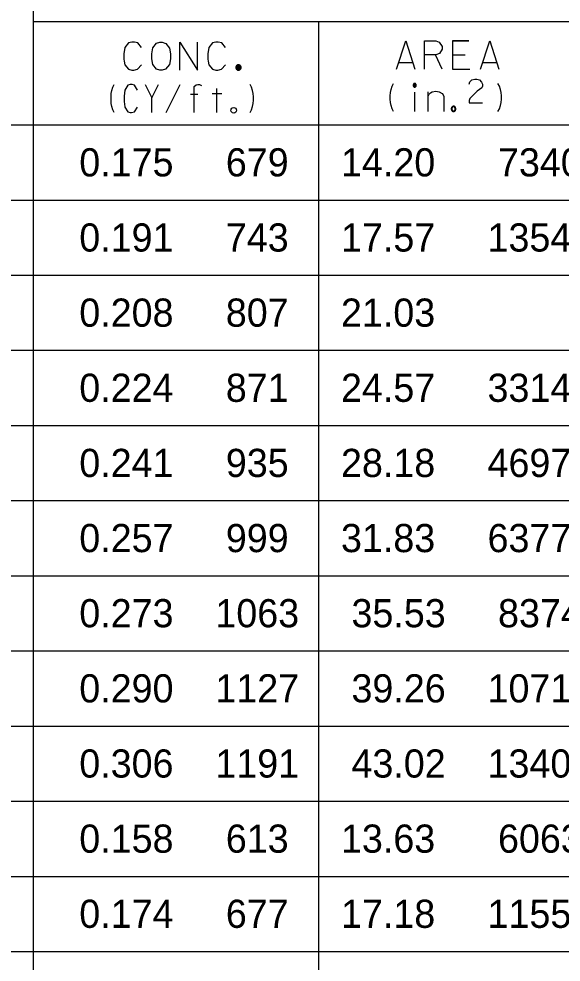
# Model space of a CAD drawing. Extents: x 635698 to 639877, y 296617 to 300175.
# Drawn here: x 639197.6 to 639255.4, y 298708.2 to 298808.6 of the extents above; entities that cross this region are included whole.
import ezdxf

# ---------------------------------------------------------------- set-up
doc = ezdxf.new("R2010")
doc.units = 0
for name, color, linetype in [('1', 7, 'Continuous'), ('2', 7, 'Continuous'), ('3', 7, 'Continuous')]:
    doc.layers.add(name, color=color, linetype=linetype)

msp = doc.modelspace()

# ---------------------------------------------------------------- linework, layer by layer
at = {"layer": '1'}
msp.add_circle((639220.51, 298798.88), 0.301, dxfattribs=at)
at = {"layer": '2'}
for p, q in [((639199.16, 298814.79), (639199.16, 298581.29)), ((639405.11, 298808.29), (639199.16, 298808.29)), ((639229.55, 298808.29), (639229.55, 298581.29)), ((639405.11, 298797.29), (638853.27, 298797.29)), ((639405.11, 298789.29), (638853.27, 298789.29)), ((639405.11, 298781.29), (638853.27, 298781.29)), ((639405.11, 298773.29), (638853.27, 298773.29)), ((639405.11, 298765.29), (638853.27, 298765.29)), ((639405.11, 298757.29), (638853.27, 298757.29)), ((639405.11, 298749.29), (638853.27, 298749.29)), ((639405.11, 298741.29), (638853.27, 298741.29)), ((639405.11, 298733.29), (638853.27, 298733.29)), ((639405.11, 298725.29), (638853.27, 298725.29)), ((639405.11, 298725.29), (638853.27, 298725.29)), ((639405.11, 298717.29), (638853.27, 298717.29)), ((639405.11, 298709.29), (638853.27, 298709.29))]:
    msp.add_line(p, q, dxfattribs=at)
at = {"layer": '3'}
for points in [[(639210.68, 298805.56), (639210.31, 298806.06), (639209.93, 298806.15), (639209.67, 298806.15), (639209.31, 298806.06), (639208.91, 298805.56), (639208.82, 298804.9), (639208.82, 298804.55), (639208.82, 298804.31), (639208.84, 298804.1), (639208.91, 298803.72), (639209.31, 298803.25), (639209.67, 298803.15), (639209.88, 298803.15), (639210.28, 298803.25), (639210.68, 298803.72)], [(639212.65, 298806.15), (639212.88, 298806.15), (639213.29, 298805.99), (639213.66, 298805.49), (639213.76, 298804.9), (639213.76, 298804.36), (639213.66, 298803.77), (639213.26, 298803.27), (639212.88, 298803.15), (639212.65, 298803.15), (639212.29, 298803.27), (639211.89, 298803.77), (639211.8, 298804.36), (639211.8, 298804.9), (639211.89, 298805.52), (639212.29, 298806.01), (639212.65, 298806.15)], [(639214.78, 298803.15), (639214.78, 298806.15), (639216.64, 298803.15), (639216.64, 298806.15)], [(639219.62, 298805.56), (639219.24, 298806.06), (639218.87, 298806.15), (639218.61, 298806.15), (639218.25, 298806.06), (639217.85, 298805.56), (639217.75, 298804.9), (639217.75, 298804.55), (639217.75, 298804.31), (639217.78, 298804.1), (639217.85, 298803.72), (639218.25, 298803.25), (639218.61, 298803.15), (639218.82, 298803.15), (639219.22, 298803.25), (639219.62, 298803.72)], [(639237.86, 298803.27), (639238.85, 298806.27), (639239.82, 298803.27)], [(639240.84, 298803.27), (639240.84, 298806.27), (639242.04, 298806.27), (639242.4, 298806.15), (639242.7, 298805.68), (639242.7, 298805.39), (639242.42, 298804.92), (639242.04, 298804.8), (639240.84, 298804.8)], [(639245.54, 298806.27), (639243.82, 298806.27), (639243.82, 298803.27), (639245.66, 298803.27)], [(639243.82, 298806.27), (639245.54, 298806.27)], [(639246.79, 298803.27), (639247.79, 298806.27), (639248.76, 298803.27)], [(639242.7, 298803.27), (639242.02, 298804.8)], [(639243.82, 298804.78), (639245.17, 298804.78)], [(639243.82, 298804.78), (639245.17, 298804.78)], [(639238.09, 298803.98), (639239.58, 298803.98)], [(639247.03, 298803.98), (639248.52, 298803.98)], [(639221.3, 298803.44), (639221.3, 298803.47), (639221.3, 298803.5), (639221.29, 298803.53), (639221.28, 298803.55), (639221.27, 298803.58), (639221.25, 298803.61), (639221.23, 298803.63), (639221.21, 298803.65), (639221.19, 298803.67), (639221.16, 298803.69), (639221.14, 298803.7), (639221.11, 298803.71), (639221.08, 298803.72), (639221.05, 298803.72), (639221.02, 298803.72), (639220.99, 298803.72), (639220.96, 298803.72), (639220.93, 298803.71), (639220.9, 298803.7), (639220.88, 298803.69), (639220.85, 298803.67), (639220.83, 298803.65), (639220.81, 298803.63), (639220.79, 298803.61), (639220.77, 298803.58), (639220.76, 298803.55), (639220.75, 298803.53), (639220.74, 298803.5), (639220.74, 298803.47), (639220.73, 298803.44), (639220.74, 298803.41), (639220.74, 298803.38), (639220.75, 298803.35), (639220.76, 298803.32), (639220.77, 298803.3), (639220.79, 298803.27), (639220.81, 298803.25), (639220.83, 298803.23), (639220.85, 298803.21), (639220.88, 298803.19), (639220.9, 298803.18), (639220.93, 298803.17), (639220.96, 298803.16), (639220.99, 298803.15), (639221.02, 298803.15), (639221.05, 298803.15), (639221.08, 298803.16), (639221.11, 298803.17), (639221.14, 298803.18), (639221.16, 298803.19), (639221.19, 298803.21), (639221.21, 298803.23), (639221.23, 298803.25), (639221.25, 298803.27), (639221.27, 298803.3), (639221.28, 298803.32), (639221.29, 298803.35), (639221.3, 298803.38), (639221.3, 298803.41), (639221.3, 298803.44)], [(639221.24, 298803.44), (639221.24, 298803.46), (639221.24, 298803.48), (639221.23, 298803.51), (639221.23, 298803.53), (639221.21, 298803.55), (639221.2, 298803.57), (639221.19, 298803.59), (639221.17, 298803.61), (639221.15, 298803.62), (639221.13, 298803.63), (639221.11, 298803.64), (639221.09, 298803.65), (639221.07, 298803.66), (639221.04, 298803.66), (639221.02, 298803.66), (639221, 298803.66), (639220.97, 298803.66), (639220.95, 298803.65), (639220.93, 298803.64), (639220.91, 298803.63), (639220.89, 298803.62), (639220.87, 298803.61), (639220.85, 298803.59), (639220.84, 298803.57), (639220.82, 298803.55), (639220.81, 298803.53), (639220.8, 298803.51), (639220.8, 298803.48), (639220.8, 298803.46), (639220.79, 298803.44), (639220.8, 298803.41), (639220.8, 298803.39), (639220.8, 298803.37), (639220.81, 298803.35), (639220.82, 298803.33), (639220.84, 298803.31), (639220.85, 298803.29), (639220.87, 298803.27), (639220.89, 298803.26), (639220.91, 298803.24), (639220.93, 298803.23), (639220.95, 298803.22), (639220.97, 298803.22), (639221, 298803.21), (639221.02, 298803.21), (639221.04, 298803.21), (639221.07, 298803.22), (639221.09, 298803.22), (639221.11, 298803.23), (639221.13, 298803.24), (639221.15, 298803.26), (639221.17, 298803.27), (639221.19, 298803.29), (639221.2, 298803.31), (639221.21, 298803.33), (639221.23, 298803.35), (639221.23, 298803.37), (639221.24, 298803.39), (639221.24, 298803.41), (639221.24, 298803.44)], [(639221.18, 298803.44), (639221.18, 298803.46), (639221.18, 298803.47), (639221.18, 298803.49), (639221.17, 298803.51), (639221.16, 298803.52), (639221.15, 298803.54), (639221.14, 298803.55), (639221.13, 298803.56), (639221.12, 298803.57), (639221.1, 298803.58), (639221.09, 298803.59), (639221.07, 298803.59), (639221.05, 298803.6), (639221.04, 298803.6), (639221.02, 298803.6), (639221, 298803.6), (639220.98, 298803.6), (639220.97, 298803.59), (639220.95, 298803.59), (639220.94, 298803.58), (639220.92, 298803.57), (639220.91, 298803.56), (639220.9, 298803.55), (639220.89, 298803.54), (639220.88, 298803.52), (639220.87, 298803.51), (639220.86, 298803.49), (639220.86, 298803.47), (639220.86, 298803.46), (639220.85, 298803.44), (639220.86, 298803.42), (639220.86, 298803.4), (639220.86, 298803.39), (639220.87, 298803.37), (639220.88, 298803.36), (639220.89, 298803.34), (639220.9, 298803.33), (639220.91, 298803.32), (639220.92, 298803.3), (639220.94, 298803.3), (639220.95, 298803.29), (639220.97, 298803.28), (639220.98, 298803.28), (639221, 298803.27), (639221.02, 298803.27), (639221.04, 298803.27), (639221.05, 298803.28), (639221.07, 298803.28), (639221.09, 298803.29), (639221.1, 298803.3), (639221.12, 298803.3), (639221.13, 298803.32), (639221.14, 298803.33), (639221.15, 298803.34), (639221.16, 298803.36), (639221.17, 298803.37), (639221.18, 298803.39), (639221.18, 298803.4), (639221.18, 298803.42), (639221.18, 298803.44)], [(639221.12, 298803.44), (639221.12, 298803.45), (639221.12, 298803.46), (639221.12, 298803.47), (639221.12, 298803.48), (639221.11, 298803.49), (639221.1, 298803.5), (639221.1, 298803.51), (639221.09, 298803.52), (639221.08, 298803.52), (639221.07, 298803.53), (639221.06, 298803.53), (639221.05, 298803.54), (639221.04, 298803.54), (639221.03, 298803.54), (639221.02, 298803.54), (639221.01, 298803.54), (639221, 298803.54), (639220.99, 298803.54), (639220.98, 298803.53), (639220.97, 298803.53), (639220.96, 298803.52), (639220.95, 298803.52), (639220.94, 298803.51), (639220.93, 298803.5), (639220.93, 298803.49), (639220.92, 298803.48), (639220.92, 298803.47), (639220.92, 298803.46), (639220.91, 298803.45), (639220.91, 298803.44), (639220.91, 298803.43), (639220.92, 298803.42), (639220.92, 298803.41), (639220.92, 298803.4), (639220.93, 298803.39), (639220.93, 298803.38), (639220.94, 298803.37), (639220.95, 298803.36), (639220.96, 298803.35), (639220.97, 298803.35), (639220.98, 298803.34), (639220.99, 298803.34), (639221, 298803.34), (639221.01, 298803.33), (639221.02, 298803.33), (639221.03, 298803.33), (639221.04, 298803.34), (639221.05, 298803.34), (639221.06, 298803.34), (639221.07, 298803.35), (639221.08, 298803.35), (639221.09, 298803.36), (639221.1, 298803.37), (639221.1, 298803.38), (639221.11, 298803.39), (639221.12, 298803.4), (639221.12, 298803.41), (639221.12, 298803.42), (639221.12, 298803.43), (639221.12, 298803.44)], [(639221.06, 298803.44), (639221.06, 298803.44), (639221.06, 298803.45), (639221.06, 298803.45), (639221.06, 298803.46), (639221.06, 298803.46), (639221.06, 298803.46), (639221.05, 298803.47), (639221.05, 298803.47), (639221.05, 298803.47), (639221.04, 298803.48), (639221.04, 298803.48), (639221.03, 298803.48), (639221.03, 298803.48), (639221.02, 298803.48), (639221.02, 298803.48), (639221.01, 298803.48), (639221.01, 298803.48), (639221.01, 298803.48), (639221, 298803.48), (639221, 298803.48), (639220.99, 298803.47), (639220.99, 298803.47), (639220.99, 298803.47), (639220.98, 298803.46), (639220.98, 298803.46), (639220.98, 298803.46), (639220.98, 298803.45), (639220.98, 298803.45), (639220.97, 298803.44), (639220.97, 298803.44), (639220.97, 298803.43), (639220.98, 298803.43), (639220.98, 298803.42), (639220.98, 298803.42), (639220.98, 298803.42), (639220.98, 298803.41), (639220.99, 298803.41), (639220.99, 298803.4), (639220.99, 298803.4), (639221, 298803.4), (639221, 298803.4), (639221.01, 298803.4), (639221.01, 298803.39), (639221.01, 298803.39), (639221.02, 298803.39), (639221.02, 298803.39), (639221.03, 298803.39), (639221.03, 298803.4), (639221.04, 298803.4), (639221.04, 298803.4), (639221.05, 298803.4), (639221.05, 298803.4), (639221.05, 298803.41), (639221.06, 298803.41), (639221.06, 298803.42), (639221.06, 298803.42), (639221.06, 298803.42), (639221.06, 298803.43), (639221.06, 298803.43), (639221.06, 298803.44)], [(639237.55, 298798.74), (639237.4, 298799.05), (639237.28, 298799.38), (639237.2, 298799.71), (639237.16, 298800.07), (639237.16, 298800.42), (639237.2, 298800.78), (639237.28, 298801.11), (639237.4, 298801.44), (639237.55, 298801.74)], [(639239.95, 298801.55), (639239.95, 298801.57), (639239.95, 298801.59), (639239.95, 298801.61), (639239.94, 298801.63), (639239.93, 298801.64), (639239.92, 298801.66), (639239.91, 298801.68), (639239.9, 298801.69), (639239.89, 298801.71), (639239.87, 298801.72), (639239.86, 298801.73), (639239.84, 298801.73), (639239.82, 298801.74), (639239.81, 298801.74), (639239.79, 298801.74), (639239.77, 298801.74), (639239.75, 298801.74), (639239.74, 298801.73), (639239.72, 298801.73), (639239.71, 298801.72), (639239.69, 298801.71), (639239.68, 298801.69), (639239.67, 298801.68), (639239.65, 298801.66), (639239.65, 298801.64), (639239.64, 298801.63), (639239.63, 298801.61), (639239.63, 298801.59), (639239.62, 298801.57), (639239.62, 298801.55), (639239.62, 298801.53), (639239.63, 298801.5), (639239.63, 298801.48), (639239.64, 298801.47), (639239.65, 298801.45), (639239.65, 298801.43), (639239.67, 298801.41), (639239.68, 298801.4), (639239.69, 298801.39), (639239.71, 298801.37), (639239.72, 298801.37), (639239.74, 298801.36), (639239.75, 298801.35), (639239.77, 298801.35), (639239.79, 298801.35), (639239.81, 298801.35), (639239.82, 298801.35), (639239.84, 298801.36), (639239.86, 298801.37), (639239.87, 298801.37), (639239.89, 298801.39), (639239.9, 298801.4), (639239.91, 298801.41), (639239.92, 298801.43), (639239.93, 298801.45), (639239.94, 298801.47), (639239.95, 298801.48), (639239.95, 298801.5), (639239.95, 298801.53), (639239.95, 298801.55)], [(639245.59, 298801.67), (639245.67, 298801.91), (639245.89, 298802.11), (639246.18, 298802.19), (639246.4, 298802.19), (639246.7, 298802.11), (639246.91, 298801.89), (639247.01, 298801.67), (639247.01, 298801.46), (639246.93, 298801.28), (639246.44, 298800.91), (639245.67, 298800.12), (639245.59, 298799.92), (639245.59, 298799.69), (639247.01, 298799.69)], [(639248.66, 298798.74), (639248.81, 298799.05), (639248.93, 298799.38), (639249.01, 298799.71), (639249.05, 298800.07), (639249.05, 298800.42), (639249.01, 298800.78), (639248.93, 298801.11), (639248.81, 298801.44), (639248.66, 298801.74)], [(639207.79, 298798.64), (639207.65, 298798.94), (639207.54, 298799.27), (639207.47, 298799.6), (639207.44, 298799.96), (639207.44, 298800.31), (639207.47, 298800.67), (639207.54, 298801), (639207.65, 298801.33), (639207.79, 298801.64)], [(639210.25, 298801.04), (639209.96, 298801.54), (639209.68, 298801.64), (639209.48, 298801.64), (639209.22, 298801.54), (639208.92, 298801.04), (639208.84, 298800.38), (639208.84, 298800.03), (639208.84, 298799.79), (639208.86, 298799.58), (639208.92, 298799.2), (639209.22, 298798.73), (639209.48, 298798.64), (639209.64, 298798.64), (639209.94, 298798.73), (639210.25, 298799.2)], [(639211.08, 298801.64), (639211.79, 298800.19), (639212.5, 298801.64)], [(639213.31, 298798.64), (639214.79, 298801.64)], [(639216.29, 298798.64), (639216.29, 298801.42), (639216.51, 298801.59), (639216.7, 298801.64), (639216.88, 298801.61), (639217.07, 298801.52)], [(639218.72, 298798.64), (639218.72, 298801.19)], [(639222.25, 298798.64), (639222.39, 298798.94), (639222.5, 298799.27), (639222.57, 298799.6), (639222.61, 298799.96), (639222.61, 298800.31), (639222.57, 298800.67), (639222.5, 298801), (639222.39, 298801.33), (639222.25, 298801.64)], [(639239.9, 298801.55), (639239.9, 298801.56), (639239.9, 298801.57), (639239.9, 298801.59), (639239.89, 298801.6), (639239.89, 298801.61), (639239.88, 298801.63), (639239.87, 298801.64), (639239.86, 298801.65), (639239.86, 298801.66), (639239.85, 298801.67), (639239.83, 298801.67), (639239.82, 298801.68), (639239.81, 298801.68), (639239.8, 298801.68), (639239.79, 298801.68), (639239.78, 298801.68), (639239.76, 298801.68), (639239.75, 298801.68), (639239.74, 298801.67), (639239.73, 298801.67), (639239.72, 298801.66), (639239.71, 298801.65), (639239.7, 298801.64), (639239.69, 298801.63), (639239.69, 298801.61), (639239.68, 298801.6), (639239.68, 298801.59), (639239.68, 298801.57), (639239.67, 298801.56), (639239.67, 298801.55), (639239.67, 298801.53), (639239.68, 298801.52), (639239.68, 298801.5), (639239.68, 298801.49), (639239.69, 298801.48), (639239.69, 298801.46), (639239.7, 298801.45), (639239.71, 298801.44), (639239.72, 298801.43), (639239.73, 298801.43), (639239.74, 298801.42), (639239.75, 298801.42), (639239.76, 298801.41), (639239.78, 298801.41), (639239.79, 298801.41), (639239.8, 298801.41), (639239.81, 298801.41), (639239.82, 298801.42), (639239.83, 298801.42), (639239.85, 298801.43), (639239.86, 298801.43), (639239.86, 298801.44), (639239.87, 298801.45), (639239.88, 298801.46), (639239.89, 298801.48), (639239.89, 298801.49), (639239.9, 298801.5), (639239.9, 298801.52), (639239.9, 298801.53), (639239.9, 298801.55)], [(639239.85, 298801.55), (639239.85, 298801.55), (639239.85, 298801.56), (639239.85, 298801.57), (639239.85, 298801.58), (639239.84, 298801.58), (639239.84, 298801.59), (639239.84, 298801.6), (639239.83, 298801.6), (639239.83, 298801.61), (639239.82, 298801.61), (639239.81, 298801.62), (639239.81, 298801.62), (639239.8, 298801.62), (639239.79, 298801.62), (639239.79, 298801.62), (639239.78, 298801.62), (639239.77, 298801.62), (639239.77, 298801.62), (639239.76, 298801.62), (639239.76, 298801.61), (639239.75, 298801.61), (639239.74, 298801.6), (639239.74, 298801.6), (639239.74, 298801.59), (639239.73, 298801.58), (639239.73, 298801.58), (639239.73, 298801.57), (639239.72, 298801.56), (639239.72, 298801.55), (639239.72, 298801.55), (639239.72, 298801.54), (639239.72, 298801.53), (639239.73, 298801.52), (639239.73, 298801.51), (639239.73, 298801.51), (639239.74, 298801.5), (639239.74, 298801.49), (639239.74, 298801.49), (639239.75, 298801.48), (639239.76, 298801.48), (639239.76, 298801.47), (639239.77, 298801.47), (639239.77, 298801.47), (639239.78, 298801.47), (639239.79, 298801.47), (639239.79, 298801.47), (639239.8, 298801.47), (639239.81, 298801.47), (639239.81, 298801.47), (639239.82, 298801.48), (639239.83, 298801.48), (639239.83, 298801.49), (639239.84, 298801.49), (639239.84, 298801.5), (639239.84, 298801.51), (639239.85, 298801.51), (639239.85, 298801.52), (639239.85, 298801.53), (639239.85, 298801.54), (639239.85, 298801.55)], [(639239.8, 298801.55), (639239.8, 298801.55), (639239.8, 298801.55), (639239.8, 298801.55), (639239.8, 298801.55), (639239.8, 298801.55), (639239.8, 298801.56), (639239.8, 298801.56), (639239.8, 298801.56), (639239.8, 298801.56), (639239.8, 298801.56), (639239.79, 298801.56), (639239.79, 298801.56), (639239.79, 298801.56), (639239.79, 298801.56), (639239.79, 298801.56), (639239.79, 298801.56), (639239.78, 298801.56), (639239.78, 298801.56), (639239.78, 298801.56), (639239.78, 298801.56), (639239.78, 298801.56), (639239.78, 298801.56), (639239.78, 298801.56), (639239.78, 298801.56), (639239.77, 298801.55), (639239.77, 298801.55), (639239.77, 298801.55), (639239.77, 298801.55), (639239.77, 298801.55), (639239.77, 298801.55), (639239.77, 298801.54), (639239.77, 298801.54), (639239.77, 298801.54), (639239.77, 298801.54), (639239.77, 298801.54), (639239.78, 298801.54), (639239.78, 298801.53), (639239.78, 298801.53), (639239.78, 298801.53), (639239.78, 298801.53), (639239.78, 298801.53), (639239.78, 298801.53), (639239.78, 298801.53), (639239.79, 298801.53), (639239.79, 298801.53), (639239.79, 298801.53), (639239.79, 298801.53), (639239.79, 298801.53), (639239.79, 298801.53), (639239.8, 298801.53), (639239.8, 298801.53), (639239.8, 298801.53), (639239.8, 298801.53), (639239.8, 298801.54), (639239.8, 298801.54), (639239.8, 298801.54), (639239.8, 298801.54), (639239.8, 298801.54), (639239.8, 298801.54), (639239.8, 298801.55)], [(639239.79, 298798.74), (639239.79, 298800.82)], [(639241.21, 298800.37), (639241.34, 298800.59), (639241.48, 298800.75), (639241.66, 298800.85), (639242.05, 298800.92), (639242.39, 298800.85), (639242.72, 298800.66), (639242.82, 298800.54), (639242.88, 298800.35), (639242.88, 298798.74)], [(639241.21, 298798.74), (639241.21, 298800.85)], [(639211.79, 298798.64), (639211.79, 298800.19)], [(639215.92, 298800.6), (639216.63, 298800.6)], [(639216.67, 298800.6), (639216.68, 298800.6)], [(639219.24, 298800.64), (639218.23, 298800.64)], [(639244.17, 298799.03), (639244.16, 298799.06), (639244.16, 298799.09), (639244.15, 298799.12), (639244.14, 298799.14), (639244.13, 298799.17), (639244.12, 298799.2), (639244.1, 298799.22), (639244.09, 298799.24), (639244.07, 298799.26), (639244.05, 298799.28), (639244.02, 298799.29), (639244, 298799.3), (639243.98, 298799.31), (639243.95, 298799.31), (639243.93, 298799.31), (639243.9, 298799.31), (639243.88, 298799.31), (639243.85, 298799.3), (639243.83, 298799.29), (639243.81, 298799.28), (639243.79, 298799.26), (639243.77, 298799.24), (639243.75, 298799.22), (639243.74, 298799.2), (639243.72, 298799.17), (639243.71, 298799.14), (639243.7, 298799.12), (639243.7, 298799.09), (639243.69, 298799.06), (639243.69, 298799.03), (639243.69, 298799), (639243.7, 298798.97), (639243.7, 298798.94), (639243.71, 298798.91), (639243.72, 298798.89), (639243.74, 298798.86), (639243.75, 298798.84), (639243.77, 298798.82), (639243.79, 298798.8), (639243.81, 298798.78), (639243.83, 298798.77), (639243.85, 298798.76), (639243.88, 298798.75), (639243.9, 298798.75), (639243.93, 298798.74), (639243.95, 298798.75), (639243.98, 298798.75), (639244, 298798.76), (639244.02, 298798.77), (639244.05, 298798.78), (639244.07, 298798.8), (639244.09, 298798.82), (639244.1, 298798.84), (639244.12, 298798.86), (639244.13, 298798.89), (639244.14, 298798.91), (639244.15, 298798.94), (639244.16, 298798.97), (639244.16, 298799), (639244.17, 298799.03)], [(639244.12, 298799.03), (639244.11, 298799.05), (639244.11, 298799.08), (639244.11, 298799.1), (639244.1, 298799.12), (639244.09, 298799.14), (639244.08, 298799.16), (639244.07, 298799.18), (639244.05, 298799.2), (639244.04, 298799.21), (639244.02, 298799.22), (639244, 298799.23), (639243.99, 298799.24), (639243.97, 298799.25), (639243.95, 298799.25), (639243.93, 298799.25), (639243.91, 298799.25), (639243.89, 298799.25), (639243.87, 298799.24), (639243.85, 298799.23), (639243.83, 298799.22), (639243.82, 298799.21), (639243.8, 298799.2), (639243.79, 298799.18), (639243.78, 298799.16), (639243.77, 298799.14), (639243.76, 298799.12), (639243.75, 298799.1), (639243.74, 298799.08), (639243.74, 298799.05), (639243.74, 298799.03), (639243.74, 298799.01), (639243.74, 298798.98), (639243.75, 298798.96), (639243.76, 298798.94), (639243.77, 298798.92), (639243.78, 298798.9), (639243.79, 298798.88), (639243.8, 298798.86), (639243.82, 298798.85), (639243.83, 298798.83), (639243.85, 298798.82), (639243.87, 298798.81), (639243.89, 298798.81), (639243.91, 298798.81), (639243.93, 298798.8), (639243.95, 298798.81), (639243.97, 298798.81), (639243.99, 298798.81), (639244, 298798.82), (639244.02, 298798.83), (639244.04, 298798.85), (639244.05, 298798.86), (639244.07, 298798.88), (639244.08, 298798.9), (639244.09, 298798.92), (639244.1, 298798.94), (639244.11, 298798.96), (639244.11, 298798.98), (639244.11, 298799.01), (639244.12, 298799.03)]]:
    msp.add_lwpolyline(points, dxfattribs=at)

# ---------------------------------------------------------------- texts
at = {"layer": '1'}
for s, p in [('  0.175     679     14.20      73400      4369      5169    0.708', (639201.83, 298791.84)), ('  0.191     743     17.57     135418      6319      7707    0.774', (639201.83, 298783.84)), ('  0.208     807     21.03 ', (639201.83, 298775.84)), ('  0.224     871     24.57     331440     10892     13490    0.908', (639201.83, 298767.84)), ('  0.241     935     28.18     469733     13490     16669    0.974', (639201.83, 298759.84)), ('  0.257     999     31.83     637700     16280     20035    1.041', (639201.83, 298751.84)), ('  0.273    1063     35.53     837434     19265     23570    1.108', (639201.83, 298743.84)), ('  0.290    1127     39.26    1071018     22434     27280    1.174', (639201.83, 298735.84)), ('  0.306    1191     43.02    1340530     25789     31161    1.241', (639201.83, 298727.84)), ('  0.158     613     13.63      60633      3945      4448    0.639', (639201.83, 298719.84)), ('  0.174     677     17.18     115518      5828      6724    0.705', (639201.83, 298711.84))]:
    msp.add_text(s, height=3, dxfattribs=at).set_placement(p)

doc.saveas('drawing.dxf')
